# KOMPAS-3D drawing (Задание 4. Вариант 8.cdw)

Views: Вид 8, Проекционный вид 10, Проекционный вид 15
Referenced files: Задание 4. Вариант 8.cdw
Dimensions and other numbers on the sheet: 40; 52; 25; 72; 60; 20; 140; 15; 2 отв.; 9; 16; 22; 10; 1:1; 1; 0; 2; 3; 4; 5; 6; 7; 8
